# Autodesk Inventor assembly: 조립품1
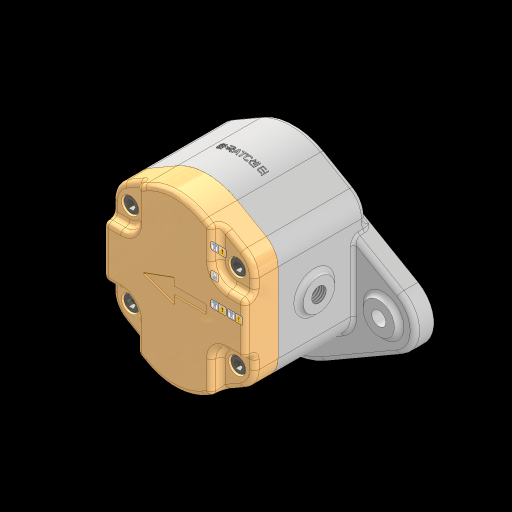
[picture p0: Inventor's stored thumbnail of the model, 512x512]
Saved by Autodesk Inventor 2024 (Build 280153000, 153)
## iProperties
Created: 2025-11
Part Number: 조립품1
Document SubType Name: Assembly
Designer: EDU03
Author: EDU03
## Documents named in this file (11)
- C:\Users\EDU03\Desktop\751103V1009\751103V1009\조립품1.iam
- C:\Users\EDU03\Desktop\751103V1009\751103V1009\본체.ipt
- C:\Users\EDU03\Desktop\751103V1009\751103V1009\3자 실링\3자 실링.ipt
- C:\Users\EDU03\Desktop\751103V1009\751103V1009\6각 구멍붙이 볼트 M6x16\6각 구멍붙이 볼트 M6x16.ipt
- C:\Users\EDU03\Desktop\751103V1009\751103V1009\DU 부시\DU 부시.ipt
- C:\Users\EDU03\Desktop\751103V1009\751103V1009\가이드 블록\가이드 블록.ipt
- C:\Users\EDU03\Desktop\751103V1009\751103V1009\구동기어\구동기어.ipt
- C:\Users\EDU03\Desktop\751103V1009\751103V1009\스퍼기어\스퍼기어.ipt
- C:\Users\EDU03\Desktop\751103V1009\751103V1009\실링\실링.ipt
- C:\Users\EDU03\Desktop\751103V1009\751103V1009\오일 실 16 30 7\오일 실 16 30 7.ipt
- C:\Users\EDU03\Desktop\751103V1009\751103V1009\커버\커버.ipt
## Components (11 placed, 5 different names)
1. 6각 구멍붙이 볼트 M6x16:1
2. DU 부시:1
3. 구동기어:1
4. DU 부시:2
5. DU 부시:3
6. DU 부시:4
7. 가이드 블록:2
8. 3자 실링:2
9. 6각 구멍붙이 볼트 M6x16:2
10. 6각 구멍붙이 볼트 M6x16:3
11. 6각 구멍붙이 볼트 M6x16:4
